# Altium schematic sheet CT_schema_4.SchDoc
size 422 x 246 mm
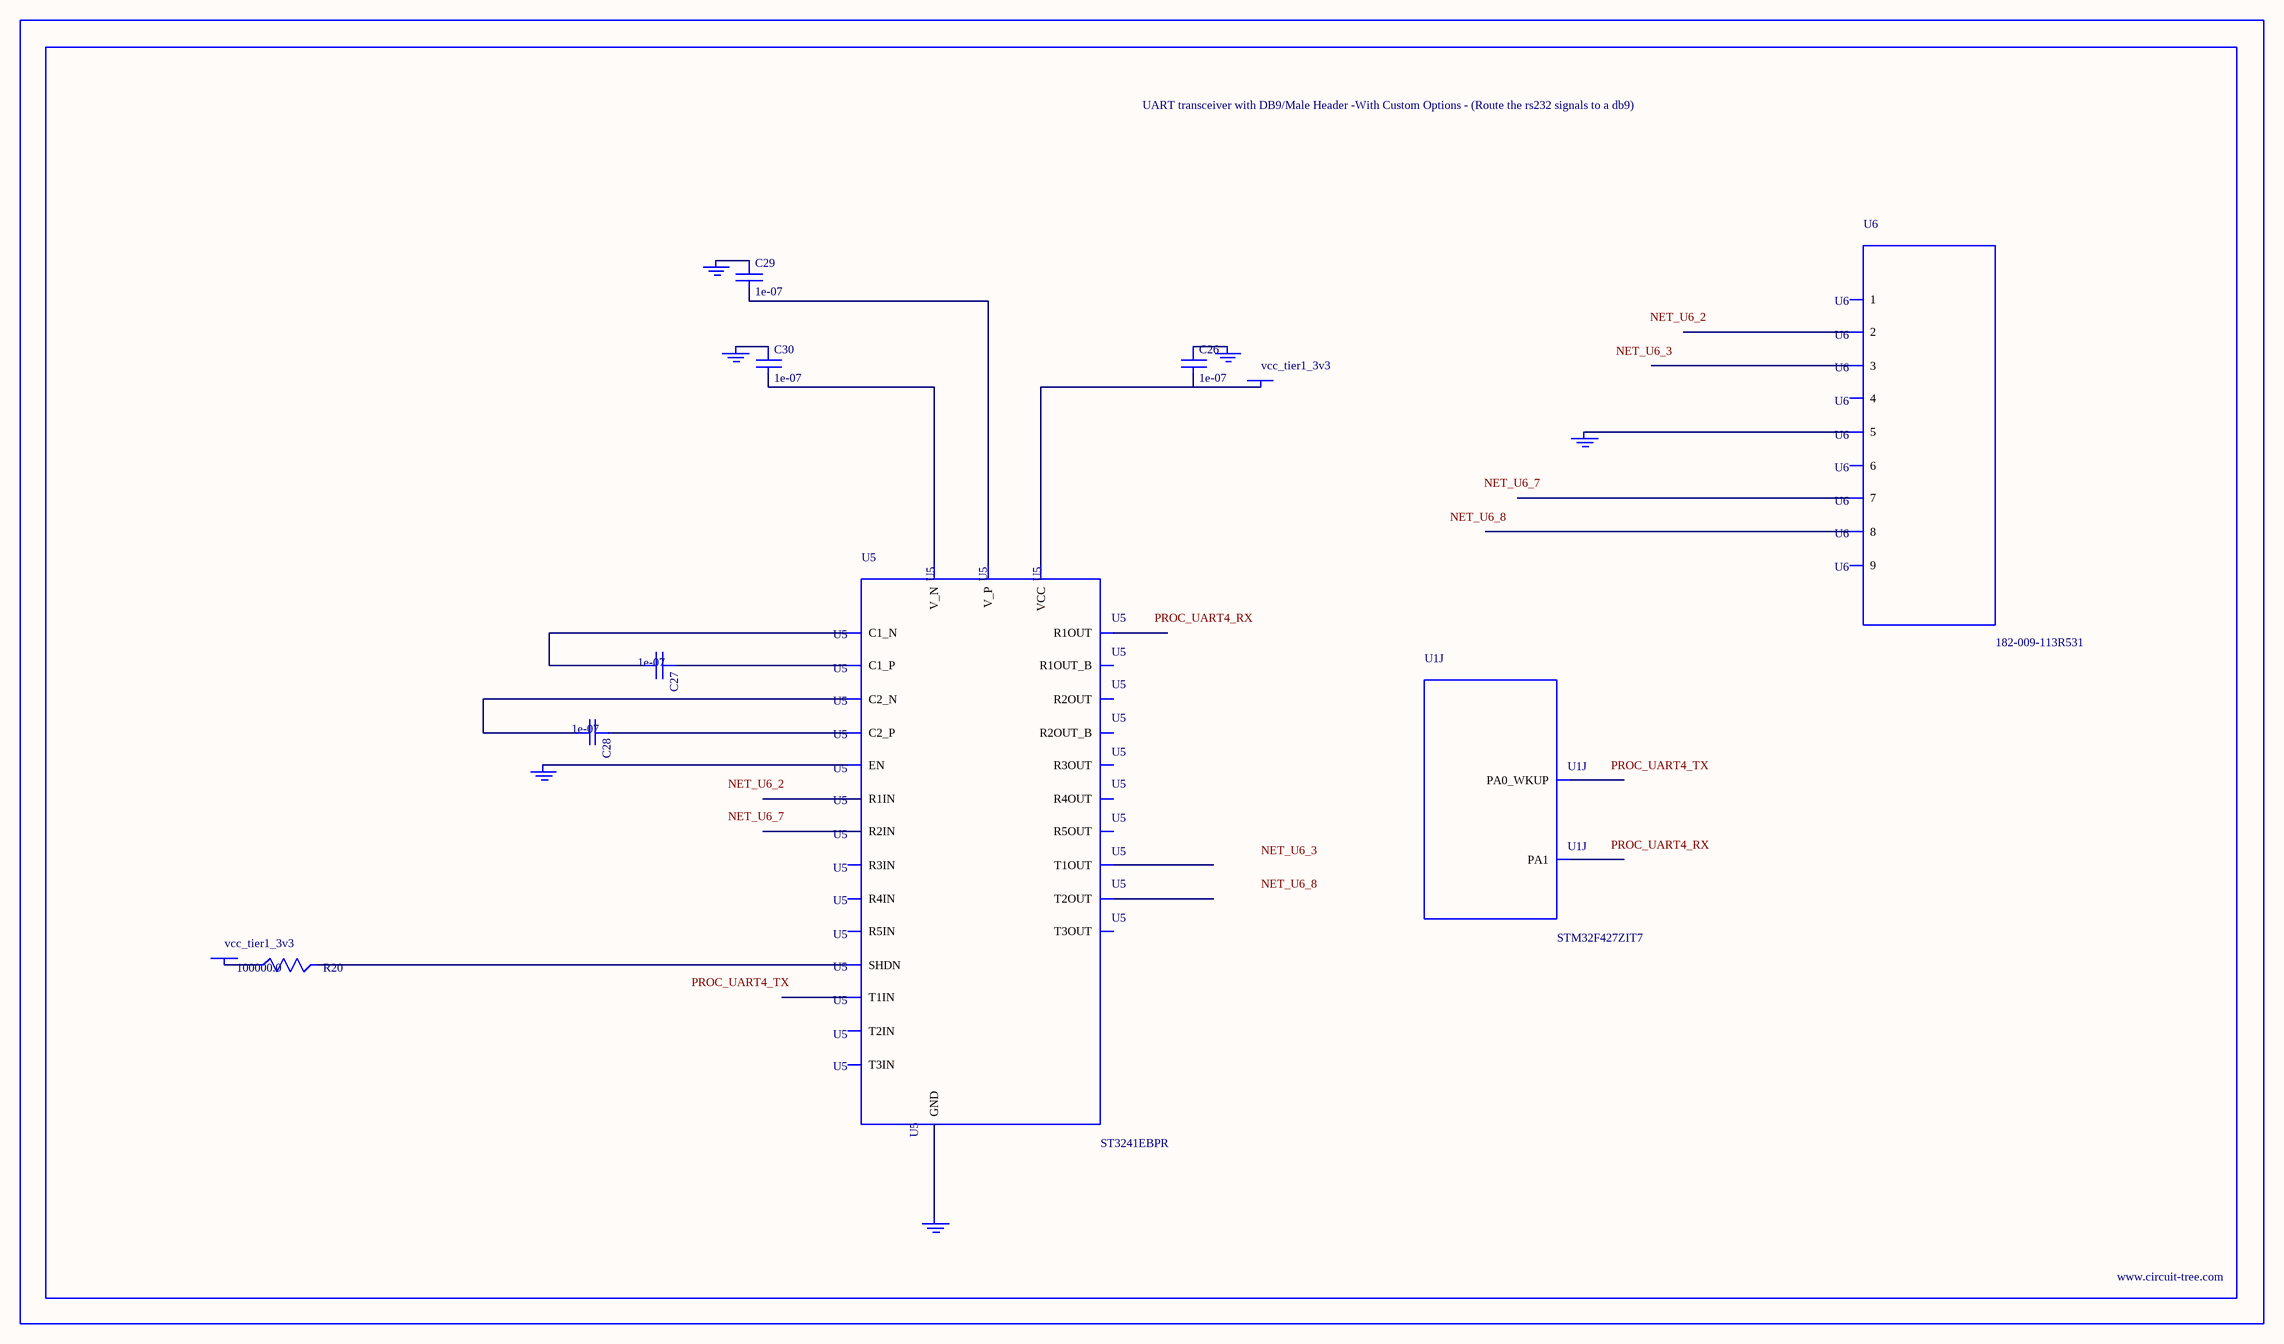
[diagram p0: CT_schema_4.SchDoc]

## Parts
BORDER3  (no value)
C26  1e-07  [C0402]
C27  1e-07  [C0402]
C28  1e-07  [C0402]
C29  1e-07  [C0402]
C30  1e-07  [C0402]
GND_INSTANCE_3_0  (no value)
GND_INSTANCE_3_1  (no value)
GND_INSTANCE_3_2  (no value)
GND_INSTANCE_3_3  (no value)
GND_INSTANCE_3_4  (no value)
GND_INSTANCE_3_5  (no value)
POWER_INSTANCE_3_0  vcc_tier1_3v3
POWER_INSTANCE_3_1  vcc_tier1_3v3
R20  100000.0  [R0603]
U1  STM32F427ZIT7  [LQFP144]  (part J of 13)
U5  ST3241EBPR  [SSOP-28]
U6  182-009-113R531  [182-009-MALE]

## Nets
NetC26_1: C26.1 GND_INSTANCE_3_2.0(GND)
NetC26_2: C26.2 POWER_INSTANCE_3_1.0(PWR) U5.26(VCC)
NetC27_1: C27.1 U5.28(C1_P)
NetC27_2: C27.2 U5.24(C1_N)
NetC28_1: C28.1 U5.1(C2_P)
NetC28_2: C28.2 U5.2(C2_N)
NetC29_1: C29.1 GND_INSTANCE_3_3.0(GND)
NetC29_2: C29.2 U5.27(V_P)
NetC30_1: C30.1 GND_INSTANCE_3_0.0(GND)
NetC30_2: C30.2 U5.3(V_N)
NetGND_INSTANCE_3_1_0: GND_INSTANCE_3_1.0(GND) U5.23(EN)
NetGND_INSTANCE_3_4_0: GND_INSTANCE_3_4.0(GND) U5.25(GND)
NetGND_INSTANCE_3_5_0: GND_INSTANCE_3_5.0(GND) U6.5
NetPOWER_INSTANCE_3_0_0: POWER_INSTANCE_3_0.0(PWR) R20.1
NetR20_2: R20.2 U5.22(SHDN)

Not connected (* = marked no-connect by the designer): U1 34(PA0_WKUP) 35(PA1); U5 4(R1IN) 5(R2IN) 6(R3IN) 7(R4IN) 8(R5IN) 9(T1OUT) 10(T2OUT) 11(T3OUT) 12(T3IN) 13(T2IN) 14(T1IN) 15(R5OUT) 16(R4OUT) 17(R3OUT) 18(R2OUT) 19(R1OUT) 20(R2OUT_B) 21(R1OUT_B); U6 1 2 3 4 6 7 8 9

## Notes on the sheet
- Labels drawn without touching a wire or pin: NET_U6_2, NET_U6_3, NET_U6_7, NET_U6_8, PROC_UART4_RX, PROC_UART4_TX

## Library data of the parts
BORDER3 = BORDER_PAGE3
C26-C30 = C0402C104K3RACTU
GND_INSTANCE_3_0-GND_INSTANCE_3_5 = GND
POWER_INSTANCE_3_0 POWER_INSTANCE_3_1 = PWR
R20 = RC0603JR-07100KL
